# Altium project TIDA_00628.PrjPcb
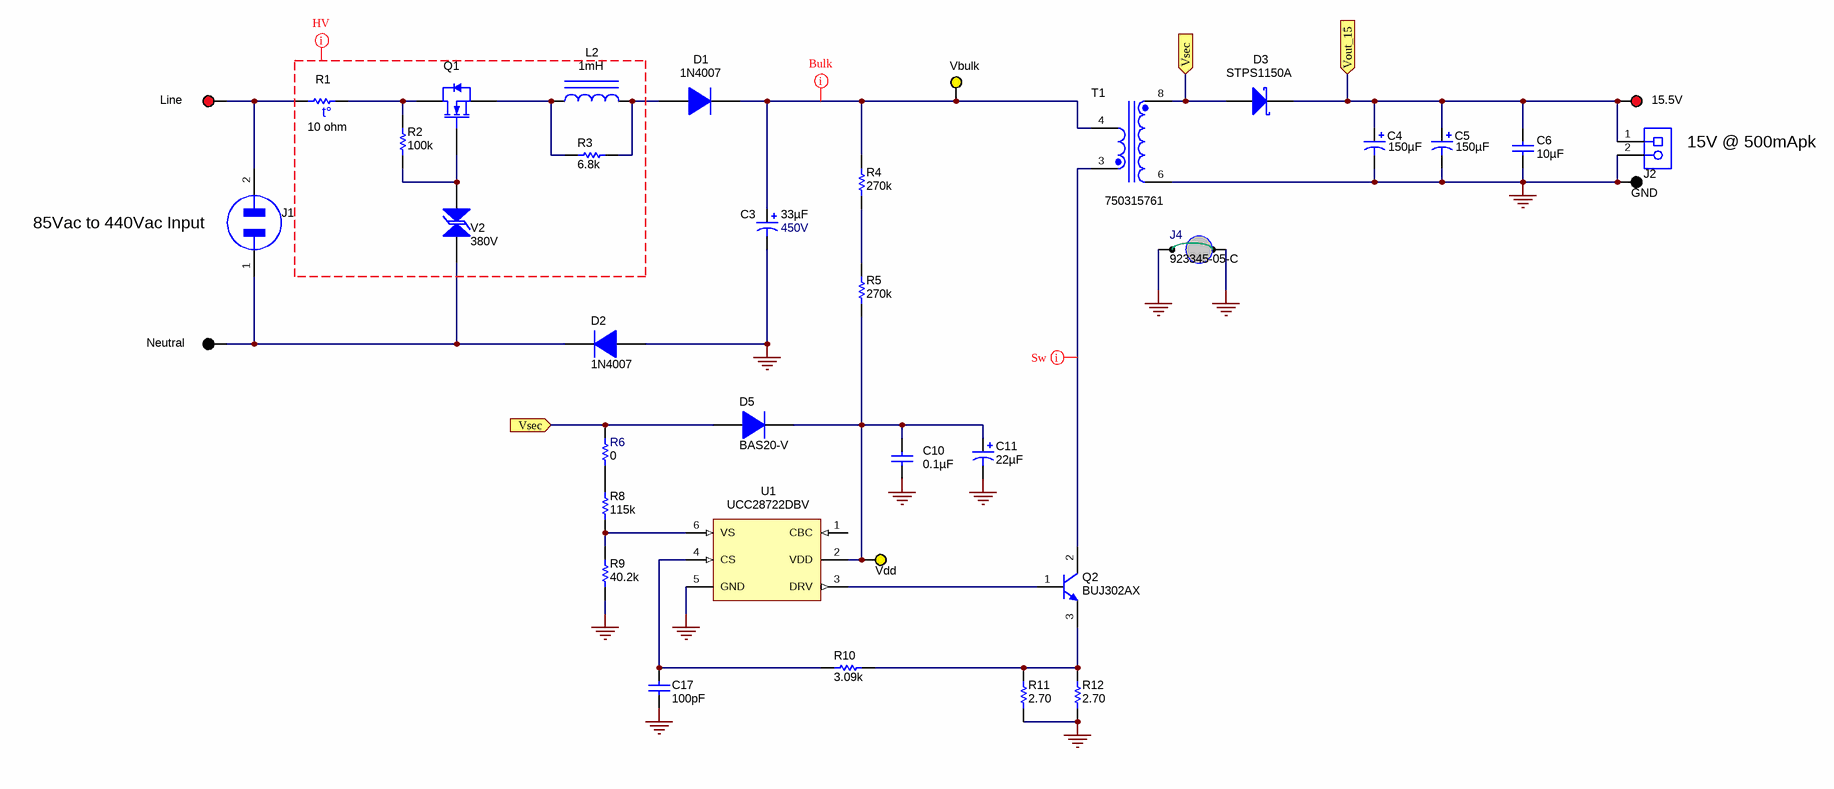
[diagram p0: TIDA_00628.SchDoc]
CopyrightYear: 2015; EVM_Orderable: N/A; PCB_Layout: Brian Gaynor; PCB_Rev: E1; PRJ_Engineer: Billy Long; PRJ_Number: TIDA_00628; PRJ_Title: TIDA_00628; SCH_Rev: E1; TechSupport: http://www.ti.com/support
2 sheets, 59 parts. Net scope: flat (ports and power ports of the same name join across sheets).
Board file: TIDA_00628.PcbDoc
Sheets:
  TIDA_00628.SchDoc
  TIDA_00628_Hardware.SchDoc

## Sheet TIDA_00628.SchDoc
size 431 x 279 mm; Date: Not shown in title block; ApprovedBy: Not shown in title block; CheckedBy: Not shown in title block; Author: Not shown in title block; CompanyName: Not shown in title block; Engineer: Not shown in title block; Organization: Not shown in title block; Address1: Not shown in title block; Address2: Not shown in title block; Address3: Not shown in title block; Address4: Not shown in title block; DocumentNumber: 1; Revision: Use project parameter SCH_Rev; SheetNumber: 1; SheetTotal: 2; PageSetup: Record=PageOptions¦CenterHorizontal=True¦CenterVertical=True¦PrintScale=0.94¦XCorrection=1.00¦YCorrection=1.00¦PrintKind=0¦BorderSize=5000000¦LeftOffset=0¦BottomOffset=0¦Orientation=2¦PaperLength=4200¦PaperWidth=2970¦Scale=100¦PaperSource=7¦PrintQuality=600¦MediaType=1¦DitherType=10¦PrintScaleMode=1¦PaperKind=A3¦PaperIndex=8

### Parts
15.5V  5000  [Keystone5000]  (value not drawn)
C3  value 33µF  VDC_V: 450V  [CAPPR5-12.5X20_HorizontalUp]  (hidden comment: 450BXW33MEFC12.5X25)
C4  value 150µF  [ZLH_630x1100]  (hidden comment: EKYB250ELL151MF11D)
C5  value 150µF  [ZLH_630x1100]  (hidden comment: EKYB250ELL151MF11D)
C6  ValueDisplayed: 10µF  [1210]  (hidden comment: GRM32ER71H106KA12L)
C10  ValueDisplayed: 0.1µF  [0603]  (hidden comment: 06035C104KAT2A)
C11  ValueDisplayed: 22µF  [SM_RADIAL_5MM]  (hidden comment: UUD1V220MCL1GS)
C17  ValueDisplayed: 100pF  [0603]  (hidden comment: 06033C101KAT2A)
D1  1N4007  [DO-41]
D2  1N4007  [DO-41]
D3  STPS1150A  [SMA]
D5  BAS20-V  [sod-323]
GND  5001  [Keystone5001]  (value not drawn)
J1  770W-X2/10  [CONN_AC_770W-SERIES]  (value not drawn)
J2  20020110-H021A01LF  [FCI_20020110-H021A01LF]  (value not drawn)
J4  923345-05-C  [923345-05-C]
L2  value 1mH  [WE-TI_1014]  (hidden comment: 744743102)
Line  5000  [Keystone5000]  (value not drawn)
Neutral  5001  [Keystone5001]  (value not drawn)
Q1  FQPF2N80  (value not drawn)
Q2  BUJ302AX  [TO-220_FullPAK_Offset]
R1  value 10 ohm  [THERM_B57236S0]  (hidden comment: B57236S0100M000)
R2  ValueDisplayed: 100k  [2010]  (hidden comment: CRCW2010100KJNEF)
R3  ValueDisplayed: 6.8k  [2010]  (hidden comment: CRCW20106K80JNEF)
R4  ValueDisplayed: 270k  [1206]  (hidden comment: CRCW1206270KJNEA)
R5  ValueDisplayed: 270k  [1206]  (hidden comment: CRCW1206270KJNEA)
R6  ValueDisplayed: 0  [1206]  (hidden comment: CRCW12060000Z0EA)
R8  ValueDisplayed: 115k  [0805_HV]  (hidden comment: CRCW0805115KFKEA)
R9  ValueDisplayed: 40.2k  [0603]  (hidden comment: RC0603FR-0740K2L)
R10  ValueDisplayed: 3.09k  [0603]  (hidden comment: CRCW06033K09FKEA)
R11  ValueDisplayed: 2.70  [1206]  (hidden comment: RC1206FR-072R7L)
R12  ValueDisplayed: 2.70  [1206]  (hidden comment: RC1206FR-072R7L)
T1  750315761  [XFMR-EF16-V]
U1  UCC28722DBV  [DBV0006A_N]
V2  Voltage - Breakdown (Min): 380V  [DO-35]  (hidden comment: P6KE400CARL)
Vbulk  5004  [Keystone5004]  (value not drawn)
Vdd  5004  [Keystone5004]  (value not drawn)

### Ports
Vout_15, Vsec (in)

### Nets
GND: C3.2(-) C4.2(-) C5.2(-) C6.2 C10.2 C11.2(-) C17.2 D2.2(A) GND.1 J2.2 J4.1 J4.2 R9.1 R11.1 R12.1 T1.6 U1.5(GND)
Vout_15: 15.5V.1 C4.1(+) C5.1(+) C6.1 D3.1(K) J2.1 ; port Vout_15
Vsec: D3.2(A) D5.2(A) R6.2 T1.8 ; port Vsec
NetC3_1: C3.1(+) D1.1(K) R4.2 T1.4 Vbulk.1
NetC10_1: C10.1 C11.1(+) D5.1(K) R5.1 U1.2(VDD) Vdd.1
NetC17_1: C17.1 R10.1 U1.4(CS)
NetD1_2: D1.2(A) L2.2 R3.2
NetD2_1: D2.1(K) J1.1(Neutral) Neutral.1 V2.2
NetJ1_2: J1.2(Hot) Line.1 R1.1
NetL2_1: L2.1 Q1.3(S) R3.1
NetQ1_1: Q1.1(D) R1.2 R2.2
NetQ1_2: Q1.2(G) R2.1 V2.1
NetQ2_1: Q2.1(B) U1.3(DRV)
NetQ2_2: Q2.2(C) T1.3
NetQ2_3: Q2.3(E) R10.2 R11.2 R12.2
NetR4_1: R4.1 R5.2
NetR6_1: R6.1 R8.2
NetR8_1: R8.1 R9.2 U1.6(VS)

Not connected (* = marked no-connect by the designer): U1 1(CBC)

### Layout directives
rule Clearance Constraint [Clearance = 2mm]: (no net found under the mark)
rule Clearance Constraint [Clearance = 1.5mm]: NetC3_1, NetQ2_2

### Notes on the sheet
- 15V @ 500mApk
- (near J1) 85Vac to 440Vac Input

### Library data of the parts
15.5V Line = 5000: Test Point, TH, Miniature, Red; Manufacturer: Keystone; CompType: Test Point Loop; U/M: EA
C3 = Capacitor_Polarized: CAP ALUM 33UF 20% 450V RADIAL; Manufacturer: Rubycon; Polarized: Y; U/M: EA; Lifetime @ Temp.: 10000 Hrs @ 105°C; Type: Polar; Ripple Current: 330mA
C4 C5 = Capacitor_Polarized: CAP ALUM 150UF 20% 25V RADIAL; Manufacturer: United Chemi-Con; Lifetime @ Temp.: 7000 Hrs @ 105°C; Ripple Current: 540mA; Impedance: 150 mOhm
C6 = GRM32ER71H106KA12L: CAP, CERM, 10uF, 50V, +/-10%, X7R, 1210; Manufacturer: MuRata; Polarized: N; CompType: Capacitor; U/M: EA; Cap_F: 0.00001; Tolerance_%: 10; Value1: Unknown; VDC_V: 50; TaMin_C: -55; TaMax_C: 125
C10 = 06035C104KAT2A: CAP, CERM, 0.1uF, 50V, +/-10%, X7R, 0603; Manufacturer: AVX; Polarized: N; CompType: Capacitor; U/M: EA; Cap_F: 0.0000001; Tolerance_%: 10; Value1: Unknown; VDC_V: 50; TaMin_C: -55; TaMax_C: 125
C11 = UUD1V220MCL1GS: CAP, AL, 22 µF, 35 V, +/- 20%, 0.76 ohm, SMD; Manufacturer: Nichicon; Polarized: Y; CompType: Capacitor; Value: 22uF; U/M: EA; Cap_F: 0.000022; Tolerance_%: 20; VDC_V: 35; Value2: 35V; ESR_ohm: 0.76; IRMS_A: 0.15; TaMin_C: -55; TaMax_C: 105; Cap_Case: 5x5.8
C17 = 06033C101KAT2A: CAP, CERM, 100 pF, 25 V, +/- 10%, X7R, 0603; Manufacturer: AVX; Polarized: N; CompType: Capacitor; Value: 100pF; U/M: EA; Cap_F: 0.0000000001; Tolerance_%: 10; Value1: Unknown; VDC_V: 25; Value2: 25V; TaMin_C: -55; TaMax_C: 125
D1 D2 = 1N4007: Diode, P-N, 1000V, 1A, TH; Manufacturer: Fairchild Semiconductor; U/M: EA; Vf_V: 1.1; Value2: 1.1V; Io_A: 1; Vr_V: 1000; TJmax_C: 175; RJC_CperW: 50
D3 = STPS130A: Diode, Schottky, 150V, 1A, SMA; Manufacturer: ST Microelectronics; U/M: EA; Vf_V: 0.46; Value2: 0.46V; Io_A: 1; TJmax_C: 150
D5 = BAS316,115: DIODE SWITCH 200V 200MA SOD323; Manufacturer: Vishay; U/M: EA; Vf_V: 1.4; Value1: 0.25A; Vr_V: 100; Value2: 100V; TJmax_C: 150; Type: Ultrafast
GND Neutral = 5001: Test Point, TH, Miniature, Black; Manufacturer: Keystone; CompType: Test Point Loop; U/M: EA
J1 = 770W-X2/10: AC Receptacle, 2.5A, R/A, TH; Manufacturer: Qualtek Electronics Corporation; SymbolCreator: a0412235; U/M: EA
J2 = 20020110-H021A01LF: Terminal Block, 2x1, 5.08mm, TH; Manufacturer: FCI; SymbolCreator: a0412235; U/M: EA
J4 = 923345-05-C: Jumper Wire, 500mil spacing, Green, pkg of 200; Manufacturer: 3M; SymbolCreator: a0412235; U/M: EA
L2 = 7447480101: Inductor, Wirewound, Ferrite, 1000uH, 0.42A, 2.5 ohm, TH; Manufacturer: Wurth Elektronik eiSos; Ind_H: 1000.0E-6; ValueDisplayed: 1000µH; Imax_A: 0.55; Irms: 0.42A @ 40C rise; Isat: 0.55A @ 10% inductance drop; DCR_ohm: 2.5; Value1: 2.5 ohm; Value2: 0.55A; U/M: EA
Q1 = MOSFET_N: MOSFET N-CH 800V 1.5A TO-220F; Manufacturer: Fairchild Semiconductor; U/M: EA; FET Type: MOSFET N-Channel, Metal Oxide; FET Feature: Standard; Vgs(th) (Max) @ Id: 5V @ 250µA; Gate Charge (Qg) @ Vgs: 15nC @ 10V; Current - Continuous Drain (Id) @ 25°C: 1.5A (Tc); Rds On (Max) @ Id, Vgs: 6.3 Ohm @ 750mA, 10V; Power - Max: 35W; Input Capacitance (Ciss) @ Vds: 550pF @ 25V
Q2 = BJT_NPN_C3B1E2: Transistor, NPN, xxV, 4A, TO-220F; Manufacturer: NXP Semiconductors; Current - Collector Cutoff (Max): 250µA; DC Current Gain (hFE) (Min) @ Ic, Vce: 25 @ 800mA, 3V; Vce Saturation (Max) @ Ib, Ic: 1.5V @ 1A, 3.5A; Voltage - Collector Emitter Breakdown (Max): 400V; Power - Max: 26W
R1 = B57236S0100M000: Thermistor NTC, 10 ohm, 20%, Disc_11.5mmx6mm; Manufacturer: EPCOS Inc; Tolerance_%: 20; Power_W: 2.1; TaMin_C: -55; TaMax_C: 170; U/M: EA
R2 = CRCW2010100KJNEF: RES, 100 k, 5%, 0.75 W, 2010; Manufacturer: Vishay-Dale; CompType: Resistor; Value: 100k; Res_ohm: 100000; Tolerance_%: 5; Power_W: 0.75; Value2: 0.75W; VDC_V: 400; TempCo: 200 ppm/C; EIA_Code: E24; U/M: EA
R3 = CRCW20106K80JNEF: RES, 6.8 k, 5%, 0.75 W, 2010; Manufacturer: Vishay-Dale; CompType: Resistor; Value: 6.8k; Res_ohm: 6800; Value_Code: 6k80; Tolerance_%: 5; Power_W: 0.75; Value2: 0.75W; VDC_V: 400; TempCo: 200 ppm/C; EIA_Code: E24; U/M: EA
R4 R5 = CRCW1206270KJNEA: RES, 270 k, 5%, 0.25 W, 1206; Manufacturer: Vishay-Dale; CompType: Resistor; Value: 270k; Res_ohm: 270000; Tolerance_%: 5; Power_W: 0.25; Value2: 0.25W; VDC_V: 200; TempCo: 200 ppm/C; EIA_Code: E24; U/M: EA
R6 = CRCW12060000Z0EA: RES, 0, 5%, 0.25 W, 1206; Manufacturer: Vishay-Dale; CompType: Resistor; Value: 0; Value_Code: 0000; Tolerance_%: 5; Power_W: 0.25; Value2: 0.25W; VDC_V: 200; TempCo: 200 ppm/C; EIA_Code: E24; U/M: EA; AEC Category: Q200
R8 = CRCW0805115KFKEA: RES, 115 k, 1%, 0.125 W, 0805; Manufacturer: Vishay-Dale; CompType: Resistor; Value: 115k; Res_ohm: 115000; Tolerance_%: 1; Power_W: 0.125; Value2: 0.125W; VDC_V: 150; TempCo: 100 ppm/C; EIA_Code: E96; U/M: EA
R9 = RC0603FR-0740K2L: RES, 40.2 k, 1%, 0.1 W, 0603; Manufacturer: Yageo America; CompType: Resistor; Value: 40.2k; Res_ohm: 40200; Value_Code: 40k2; Tolerance_%: 1; Power_W: 0.1; Value2: 0.1W; VDC_V: 150; TempCo: 200 ppm/C; EIA_Code: E96; U/M: EA
R10 = CRCW06033K09FKEA: RES, 3.09 k, 1%, 0.1 W, 0603; Manufacturer: Vishay-Dale; CompType: Resistor; Value: 3.09k; Res_ohm: 3090; Value_Code: 3k09; Tolerance_%: 1; Power_W: 0.1; Value2: 0.1W; VDC_V: 75; TempCo: 100 ppm/C; EIA_Code: E96; U/M: EA
R11 R12 = RC1206FR-072R7L: RES, 2.70, 1%, 0.25 W, 1206; Manufacturer: Yageo America; CompType: Resistor; Value: 2.70; Res_ohm: 2.7; Value_Code: 2R70; Tolerance_%: 1; Power_W: 0.25; Value2: 0.25W; VDC_V: 200; TempCo: 200 ppm/C; U/M: EA
T1 = XFMR_1_4_INV: 1 Input 4 Output XFMR; Manufacturer: Wurth
U1 = UCC28722DBV: Constant-Voltage, Constant-Current Controller With Primary-Side Regulation, BJT Drive, DBV0006A; Alternate Manufacturer: None; Manufacturer: Texas Instruments; SymbolCreator: a0799628; CompType: IC; U/M: EA
V2 = TVS_Diode: TVS DIODE 342VWM 706VC DO15; Manufacturer: STMicroelectronics; U/M: EA; Power - Peak Pulse: 600W; Power Line Protection: No; Voltage - Reverse Standoff (Typ): 342V; Voltage - Clamping (Max) @ Ipp: 706V; Bidirectional Channels: 1; Capacitance @ Frequency: 180pF @ 1MHz; Current - Peak Pulse (10/1000µs): 5.7A (8/20µs)
Vbulk Vdd = 5004: Test Point, Miniature, Yellow, TH; Manufacturer: Keystone; CompType: Test Point Loop; U/M: EA

## Sheet TIDA_00628_Hardware.SchDoc
size 431 x 279 mm; Date: Not shown in title block; ApprovedBy: Not shown in title block; CheckedBy: Not shown in title block; Author: Not shown in title block; CompanyName: Not shown in title block; Engineer: Not shown in title block; Organization: Not shown in title block; Address1: Not shown in title block; Address2: Not shown in title block; Address3: Not shown in title block; Address4: Not shown in title block; DocumentNumber: 1; Revision: Use project parameter SCH_Rev; SheetNumber: 3; SheetTotal: 3; PageSetup: Record=PageOptions¦CenterHorizontal=True¦CenterVertical=True¦PrintScale=1.00¦XCorrection=1.00¦YCorrection=1.00¦PrintKind=0¦BorderSize=5000000¦LeftOffset=0¦BottomOffset=0¦Orientation=2¦PaperLength=1000¦PaperWidth=1000¦Scale=100¦PaperSource=15¦PrintQuality=600¦MediaType=1¦DitherType=10¦PaperKind=Letter¦PrintScaleMode=1
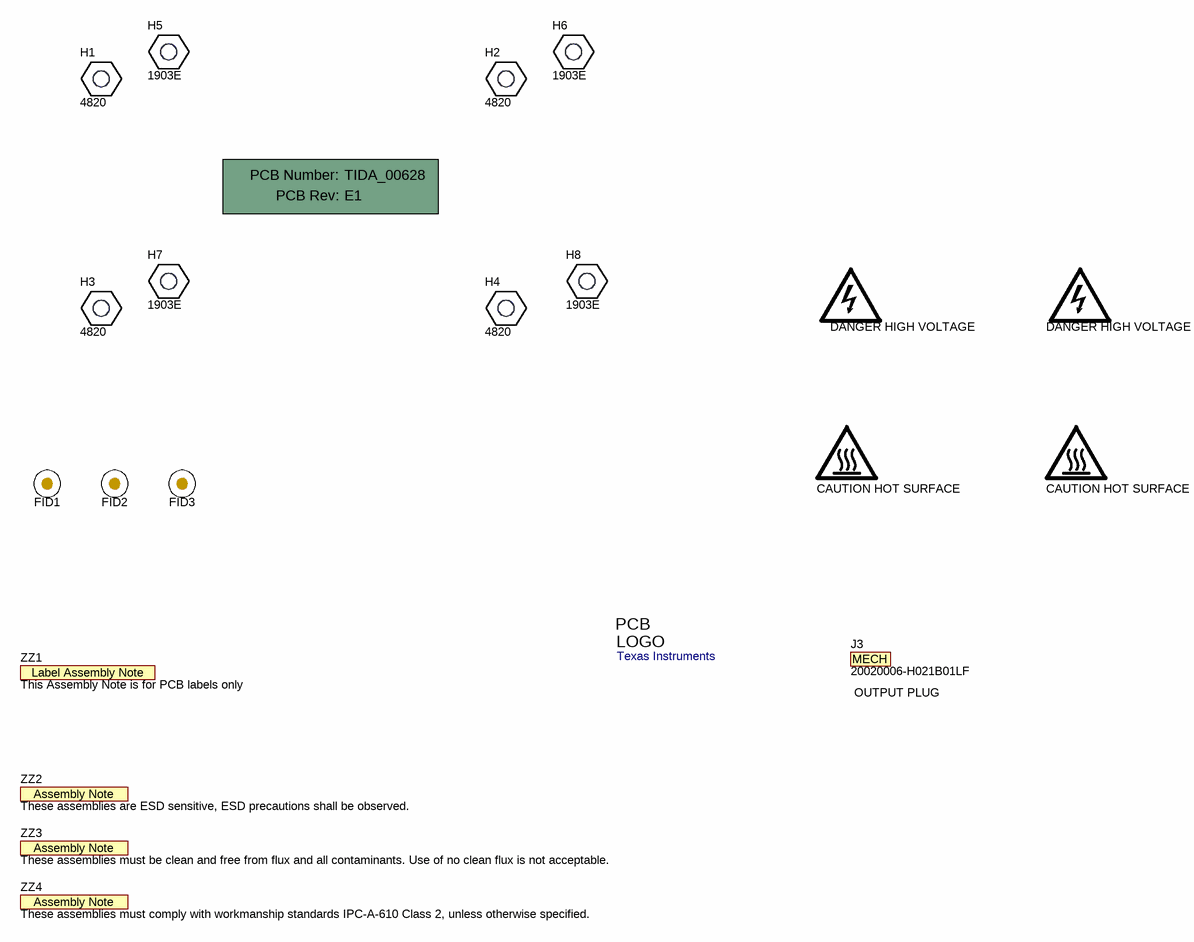
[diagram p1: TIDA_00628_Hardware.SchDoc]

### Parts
4  CAUTION HOT SURFACE  [IEC_HotSurface_Small]  (no BOM)
!PCB  Printed Circuit Board  (value not drawn)  (mechanical)
FID1  Fiducial  [Fiducial10-20]  (value not drawn)
FID2  Fiducial  [Fiducial10-20]  (value not drawn)
FID3  Fiducial  [Fiducial10-20]  (value not drawn)
H1  4820  [KEYSTONE_4820]
H2  4820  [KEYSTONE_4820]
H3  4820  [KEYSTONE_4820]
H4  4820  [KEYSTONE_4820]
H5  1903E  [KEYSTONE_1903E]
H6  1903E  [KEYSTONE_1903E]
H7  1903E  [KEYSTONE_1903E]
H8  1903E  [KEYSTONE_1903E]
J3  20020006-H021B01LF  (mechanical)
Logo1  Texas Instruments  [TI_Stacked_Overlay_Small]  (no BOM)
Logo2  DANGER HIGH VOLTAGE  [IEC_HighVoltage_Small]  (no BOM)
Logo3  DANGER HIGH VOLTAGE  [IEC_HighVoltage_Small]  (no BOM)
Logo5  CAUTION HOT SURFACE  [IEC_HotSurface_Small]  (no BOM)
ZZ1  This Assembly Note is for PCB labels only  [AssemblyNoteLabel]  (no BOM)
ZZ2  These assemblies are ESD sensitive, ESD precautions shall be observed.  [AssemblyNote]  (no BOM)
ZZ3  These assemblies must be clean and free from flux and all contaminants. Use of no clean flux is not acceptable.  [AssemblyNote]  (no BOM)
ZZ4  These assemblies must comply with workmanship standards IPC-A-610 Class 2, unless otherwise specified.  [AssemblyNote]  (no BOM)

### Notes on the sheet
- (near J3) OUTPUT PLUG

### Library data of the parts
4 Logo5 = IEC_HotSurface: IEC 61010-1 Hot Surface Warning; SymbolCreator: a0412235
!PCB = PCB: Manufacturer: Any; PartNumber: TIDA_00628; SymbolCreator: a0412235
FID1-FID3 = Fiducial: Fiducial mark.  There is nothing to buy or mount.; SymbolCreator: codlsc
H1-H4 = 4820: Standoff, Hex, 1"L #6-32 Nylon, M-F; Manufacturer: Keystone; SymbolCreator: a0412235
H5-H8 = 1903E: Standoff, Hex, 1"L #6-32 Nylon; Manufacturer: Keystone; SymbolCreator: a0412235
J3 = 20020006-H021B01LF: TERM BLOCK PLUG 2POS 5.08MM; Manufacturer: FCI; SymbolCreator: codlsc
Logo1 = TI_Logo: Texas Instrument Corporate Signature; SymbolCreator: a0412235
Logo2 Logo3 = IEC_HighVoltage: IEC 61010-1 High Voltage Warning; SymbolCreator: a0412235
ZZ1 = AssemblyNoteLabel: SymbolCreator: a0412235
ZZ2-ZZ4 = AssemblyNote: SymbolCreator: codlsc

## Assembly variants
001: not fitted FID1 FID2 FID3 J4 R6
